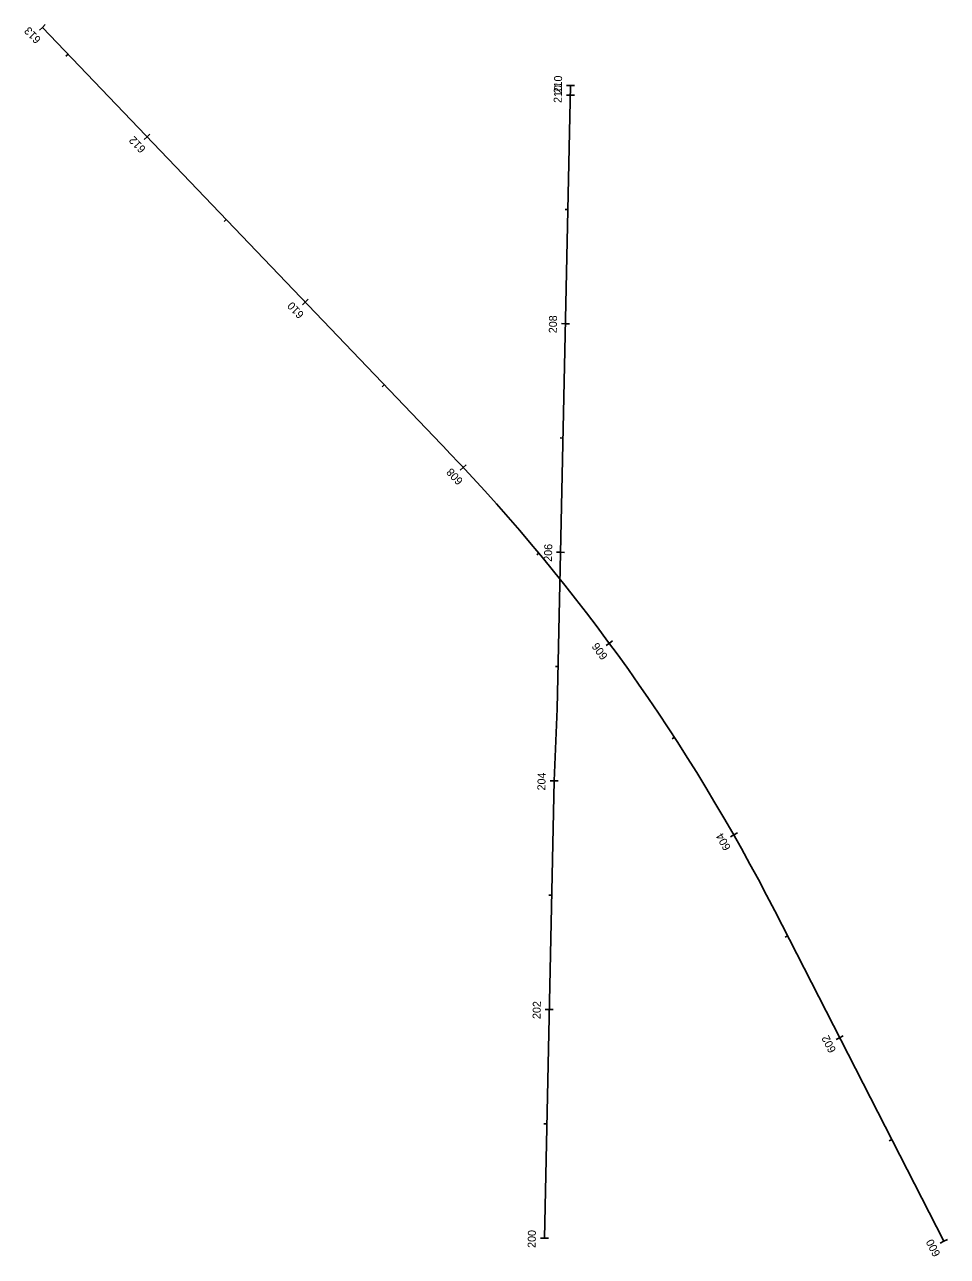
# Model space of a CAD drawing. Extents: x 596007 to 607538, y 326212 to 405053.
# Drawn here: x 596007 to 596813, y 342744 to 343822 of the extents above; entities that cross this region are included whole.
import ezdxf

# ---------------------------------------------------------------- set-up
doc = ezdxf.new("R2010")
doc.units = 0
for name, color, linetype in [('P_ALI', 7, 'Continuous'), ('P_ALI_200', 7, 'Continuous'), ('P_ALI_200_Sta', 7, 'Continuous'), ('P_ALI_200_Tic', 7, 'Continuous')]:
    doc.layers.add(name, color=color, linetype=linetype)

msp = doc.modelspace()

# ---------------------------------------------------------------- linework, layer by layer
at = {"layer": 'P_ALI'}
for points in [[(596472.2, 343223.3), (596483.8, 343768.5)], [(596469.4, 343160.3), (596472.2, 343223.3)], [(596460.9, 342760.4), (596469.4, 343160.3)]]:
    msp.add_lwpolyline(points, dxfattribs=at)
at = {"layer": 'P_ALI_200'}
for points in [[(596377.2, 343448), (596022, 343819.3)], [(596810.1, 342757.7), (596662.4, 343046.6)]]:
    msp.add_lwpolyline(points, dxfattribs=at)
msp.add_arc((595148.5, 342273), 1700, 27.0674, 43.7214, dxfattribs=at)
at = {"layer": 'P_ALI_200_Sta'}
for points in [[(596024.6, 343821.8), (596022, 343819.3)], [(596022, 343819.3), (596019.5, 343816.9)], [(596022, 343819.3), (596022, 343819.3)], [(596483.8, 343768.5), (596480.3, 343768.6)], [(596483.8, 343768.5), (596483.8, 343768.5)], [(596487.3, 343768.4), (596483.8, 343768.5)], [(596483.6, 343760.2), (596480.1, 343760.2)], [(596483.6, 343760.2), (596483.6, 343760.2)], [(596487.1, 343760.1), (596483.6, 343760.2)], [(596113.6, 343723.6), (596111, 343721.2)], [(596116.1, 343726), (596113.6, 343723.6)], [(596113.6, 343723.6), (596113.6, 343723.6)], [(596251.8, 343579.1), (596249.3, 343576.6)], [(596254.3, 343581.5), (596251.8, 343579.1)], [(596251.8, 343579.1), (596251.8, 343579.1)], [(596479.4, 343560.2), (596475.9, 343560.3)], [(596479.4, 343560.2), (596479.4, 343560.2)], [(596482.9, 343560.1), (596479.4, 343560.2)], [(596390, 343434.5), (596387.4, 343432.1)], [(596392.5, 343436.8), (596390, 343434.5)], [(596390, 343434.5), (596390, 343434.5)], [(596475.1, 343360.3), (596471.6, 343360.3)], [(596475.1, 343360.3), (596475.1, 343360.3)], [(596478.6, 343360.2), (596475.1, 343360.3)], [(596520.5, 343282.8), (596517.7, 343280.7)], [(596517.7, 343280.7), (596514.9, 343278.6)], [(596517.7, 343280.7), (596517.7, 343280.7)], [(596469.4, 343160.3), (596465.9, 343160.4)], [(596469.4, 343160.3), (596469.4, 343160.3)], [(596472.9, 343160.3), (596469.4, 343160.3)], [(596626.5, 343113), (596623.5, 343111.3)], [(596629.6, 343114.8), (596626.5, 343113)], [(596626.5, 343113), (596626.5, 343113)], [(596465.2, 342960.4), (596461.7, 342960.5)], [(596465.2, 342960.4), (596465.2, 342960.4)], [(596468.7, 342960.3), (596465.2, 342960.4)], [(596722.1, 342937.3), (596719, 342935.7)], [(596719, 342935.7), (596715.9, 342934.2)], [(596719, 342935.7), (596719, 342935.7)], [(596460.9, 342760.4), (596457.4, 342760.5)], [(596460.9, 342760.4), (596460.9, 342760.4)], [(596464.4, 342760.4), (596460.9, 342760.4)], [(596810.1, 342757.7), (596806.9, 342756.1)], [(596813.2, 342759.3), (596810.1, 342757.7)], [(596810.1, 342757.7), (596810.1, 342757.7)]]:
    msp.add_lwpolyline(points, dxfattribs=at)
at = {"layer": 'P_ALI_200_Tic'}
for points in [[(596044.5, 343795.9), (596042.6, 343794.2)], [(596481.5, 343660.2), (596479, 343660.2)], [(596182.7, 343651.3), (596180.9, 343649.6)], [(596320.9, 343506.8), (596319.1, 343505.1)], [(596477.3, 343460.2), (596474.8, 343460.3)], [(596456.1, 343359.5), (596454.2, 343357.9)], [(596473, 343260.3), (596470.5, 343260.3)], [(596574.6, 343198.5), (596572.5, 343197.1)], [(596467.3, 343060.4), (596464.8, 343060.4)], [(596673.5, 343024.8), (596671.3, 343023.6)], [(596463, 342860.4), (596460.5, 342860.5)], [(596764.5, 342846.7), (596762.3, 342845.6)]]:
    msp.add_lwpolyline(points, dxfattribs=at)

# ---------------------------------------------------------------- texts
at = {"layer": 'P_ALI_200_Sta'}
for s, rotation, p in [('613', 133.7214, (596021.3, 343809.2)), ('210', 88.7864, (596476.1, 343761.5)), ('210', 88.7864, (596476, 343753.2)), ('612', 133.7214, (596112.9, 343713.5)), ('610', 133.7214, (596251.3, 343568.7)), ('208', 88.7864, (596471.7, 343551.8)), ('608', 133.0935, (596390.3, 343423.1)), ('206', 88.7864, (596467.5, 343351.9)), ('606', 126.3528, (596516.7, 343269.4)), ('204', 88.7864, (596461.7, 343151.9)), ('604', 119.6121, (596624.2, 343101.9)), ('202', 88.7864, (596457.5, 342952)), ('602', 117.0773, (596716.2, 342924.7)), ('200', 88.7864, (596453.2, 342751.8)), ('600', 117.0773, (596807.4, 342746.4))]:
    msp.add_text(s, height=7, rotation=rotation, dxfattribs=at).set_placement(p)

doc.saveas('drawing.dxf')
